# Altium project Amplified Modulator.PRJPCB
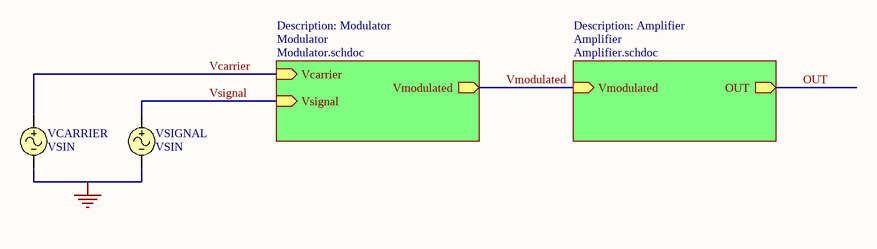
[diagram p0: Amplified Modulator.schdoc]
3 sheets, 22 parts. Net scope: hierarchical (ports join the sheet entries above them; power ports are global).
Sheets:
  Amplified Modulator.schdoc
    Amplifier = Amplifier.schdoc
    Modulator = Modulator.schdoc

## Sheet Amplified Modulator.schdoc: Amplified Modulator
size A4; Organization: Altium Limited; Address1: L3, 12a Rodborough Rd; Address2: Frenchs Forest; Address3: NSW; Address4: Australia 2086; DocumentNumber: 1; SheetNumber: 1; SheetTotal: 3

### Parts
VCARRIER  VSIN
VSIGNAL  VSIN

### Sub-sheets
Amplifier = Amplifier.schdoc: Vmodulated (in), OUT (out)  | Description: Amplifier
Modulator = Modulator.schdoc: Vmodulated (out), Vcarrier (in), Vsignal (in)  | Description: Modulator

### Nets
GND: VCARRIER.2 VSIGNAL.2
Vcarrier: VCARRIER.1 ; sheet Modulator/Vcarrier
Vmodulated: sheet Amplifier/Vmodulated, sheet Modulator/Vmodulated
Vsignal: VSIGNAL.1 ; sheet Modulator/Vsignal

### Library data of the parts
VCARRIER VSIGNAL = VSIN: Sinusoidal Voltage Source

## Sheet Amplifier.schdoc: Amplifier
size A4; Organization: Altium Limited; Address1: L3, 12a Rodborough Rd; Address2: Frenchs Forest; Address3: NSW; Address4: Australia 2086; DocumentNumber: 2; SheetNumber: 2; SheetTotal: 3
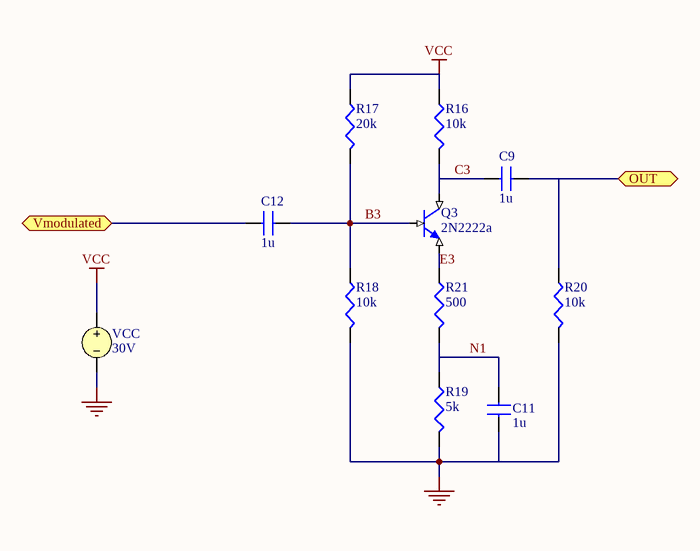
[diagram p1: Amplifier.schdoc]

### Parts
C9  1u
C11  1u
C12  1u
Q3  2N2222a
R16  10k
R17  20k
R18  10k
R19  5k
R20  10k
R21  500
VCC  30V

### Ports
OUT, Vmodulated

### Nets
GND: C11.1 R18.1(TOP) R19.1(TOP) R20.1(TOP) VCC.2
VCC: R16.2(BOT) R17.2(BOT) VCC.1
B3: C12.2 Q3.2(B) R17.1(TOP) R18.2(BOT)
C3: C9.1 Q3.1(C) R16.1(TOP)
E3: Q3.3(E) R21.2(BOT)
N1: C11.2 R19.2(BOT) R21.1(TOP)
OUT: C9.2 R20.2(BOT) ; port OUT
Vmodulated: C12.1 ; port Vmodulated

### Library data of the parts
C9 C11 C12 = CAP: Capacitor
Q3 = 2N2222a: NPN BJT
R16-R21 = RES: Resistor
VCC = VSRC: Voltage Source

## Sheet Modulator.schdoc: Modulator
size A4; Organization: Altium Limited; Address1: L3, 12a Rodborough Rd; Address2: Frenchs Forest; Address3: NSW; Address4: Australia 2086; DocumentNumber: 3; SheetNumber: 3; SheetTotal: 3
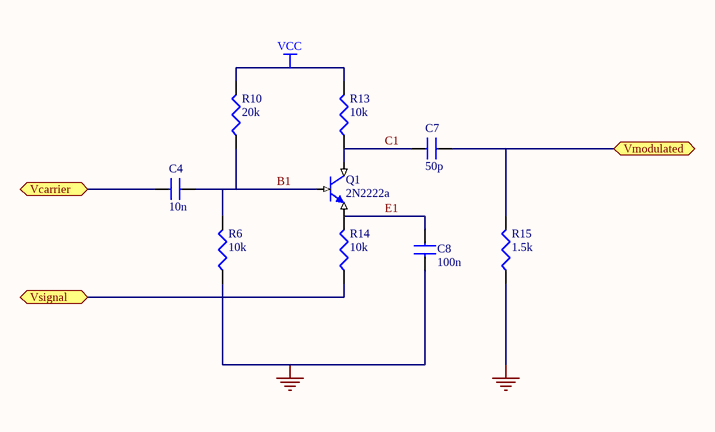
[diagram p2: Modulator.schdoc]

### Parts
C4  10n
C7  50p
C8  100n
Q1  2N2222a
R6  10k
R10  20k
R13  10k
R14  10k
R15  1.5k

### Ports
Vcarrier, Vmodulated, Vsignal

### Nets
GND: C8.1 R6.2(BOT) R15.2(BOT)
VCC: R10.1(TOP) R13.1(TOP)
B1: C4.2 Q1.2(B) R6.1(TOP) R10.2(BOT)
C1: C7.1 Q1.1(C) R13.2(BOT)
E1: C8.2 Q1.3(E) R14.1(TOP)
Vcarrier: C4.1 ; port Vcarrier
Vmodulated: C7.2 R15.1(TOP) ; port Vmodulated
Vsignal: R14.2(BOT) ; port Vsignal

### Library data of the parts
C4 C7 C8 = CAP: Capacitor
Q1 = 2N2222a: NPN BJT
R6 R10 R13-R15 = RES: Resistor

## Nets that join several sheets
GND: Amplified Modulator (VCARRIER.2 VSIGNAL.2), Amplifier (5 pins), Modulator (C8.1 R6.2 R15.2)
VCC: Amplifier (R16.2 R17.2 VCC.1), Modulator (R10.1 R13.1)
Vcarrier: Amplified Modulator (VCARRIER.1), Modulator (C4.1)
Vmodulated: Amplifier (C12.1), Modulator (C7.2 R15.1)
Vsignal: Amplified Modulator (VSIGNAL.1), Modulator (R14.2)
